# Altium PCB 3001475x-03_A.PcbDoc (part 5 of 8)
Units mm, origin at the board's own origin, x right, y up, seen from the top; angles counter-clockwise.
Board outline 100 x 72 mm, 12 copper layers (Top Layer, L2 GND, Layer 3, L4 GND, Layer 5, L6 PWR, L7 3V3, Layer 8, L9 GND, Layer 10, L11 GND, Bottom Layer), stack 1.735 mm thick; 428 components, 499 nets, 1973 pads, 1473 vias.
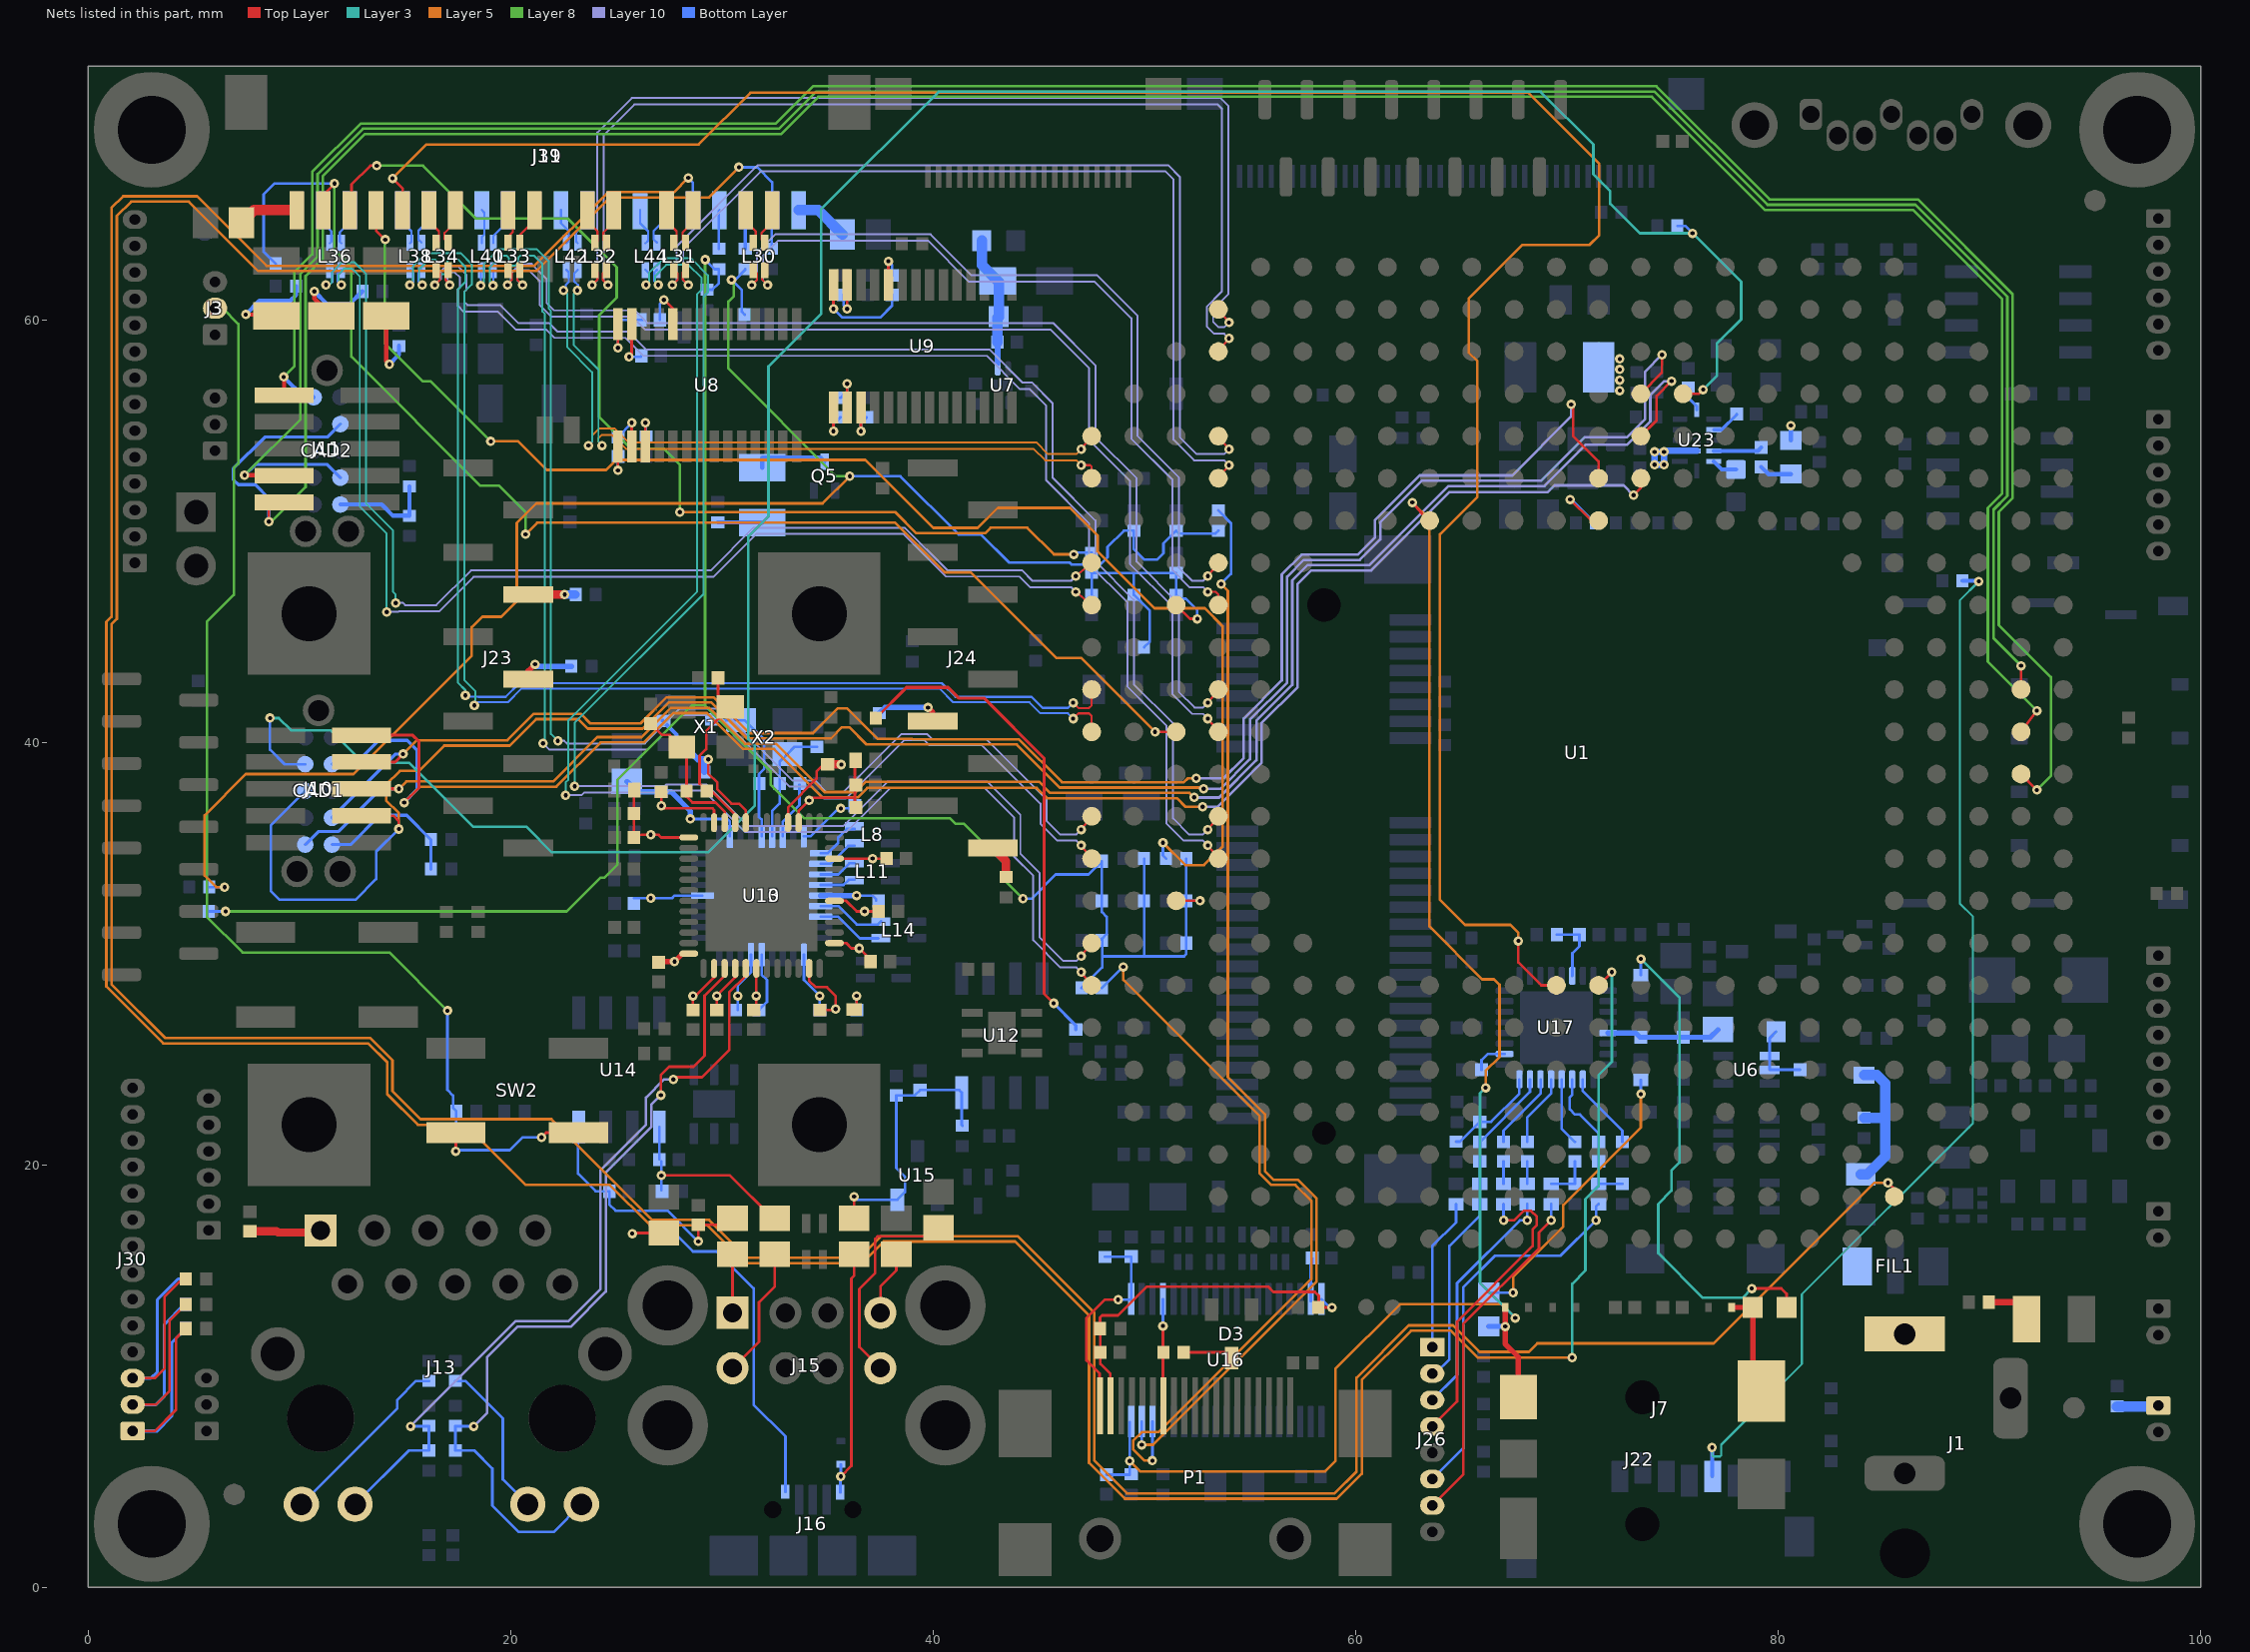
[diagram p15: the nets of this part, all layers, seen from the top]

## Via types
v1: diameter 0.45, hole 0.2, Top Layer to Bottom Layer, 1473 vias

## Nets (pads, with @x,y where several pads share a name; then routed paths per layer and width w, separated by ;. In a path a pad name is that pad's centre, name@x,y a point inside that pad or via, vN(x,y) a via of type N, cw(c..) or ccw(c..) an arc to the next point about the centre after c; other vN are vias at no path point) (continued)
HDMI_HPD: C83.2 R90.2 U1.G9 U16.19 | length 71
  Top Layer w0.125: v1(62.68,51.355) U1.G9@63.43,50.48
  Layer 5 w0.125: v1(49.305,5.98) 49.805,5.48 58.538,5.48 59.038,5.979 59.038,10.338 62.1,13.4 66.91,13.4 v1(67.555,12.755) ; v1(62.68,51.355) 63.487,50.548 63.487,31.279 65.979,28.788 66.546,28.788 66.805,28.528 66.805,25.105 66.15,24.45 v1(66.15,23.65)
  Layer 3 w0.125: v1(66.15,23.65) 65.887,23.387 65.887,14.423 v1(67.555,12.755)
  Bottom Layer w0.125: C83.2@48.2,5.335 49.305,5.335 v1(49.305,5.98) U16.19@49.305,7.83
HDMI_I2C_SCL: R99.2 U16.17 | length 35.6
  Layer 5 w0.125: v1(49,29.375) 49,28.75 55.45,22.3 55.45,19.6 56,19.05 57.15,19.05 57.9,18.3 57.9,14.592 50.658,7.35 49.875,7.35 49.462,6.937 49.462,6.538 50,6 v1(50.375,6)
  Bottom Layer w0.125: R99.2@47.98,28.375 48.98,29.375 v1(49,29.375) ; v1(50.375,6) U16.17@50.375,7.85
HDMI_I2C_SDA: R100.2 U16.18 | length 52.2
  Layer 5 w0.125: v1@49.875,6.625 v1(49.875,6.75) 50.412,6.75 58.15,14.488 58.15,18.404 57.254,19.3 56.104,19.3 55.704,19.7 55.704,22.4 53.95,24.154 53.95,47.175 v1(53.625,47.5)
  Bottom Layer w0.125: v1(49.875,6.75) U16.18@49.875,7.85 ; R100.2@53.5,50.98 54.1,50.38 54.1,47.975 v1(53.625,47.5)
HDMICEC: P1.13 R86.2 U16.23 | length 5.1
  Top Layer w0.125: P1.13@50.875,8.5 v1(50.875,12.375)
  Bottom Layer w0.125: v1(50.875,12.375) U16.23@50.875,13.65
HDMIHPD: C85.2 P1.19 R89.2 U16.20 | length 10.2
  Top Layer w0.125: P1.19@47.875,8.5 47.875,10.125 47.25,10.75 47.25,12.75 48.125,13.625 v1(48.75,13.625)
  Bottom Layer w0.125: R89.2@48.125,15.645 C85.2@49.355,15.645 ; v1(48.75,13.625) U16.20@49.35,13.625 ; U16.20@49.375,13.65 C85.2@49.375,15.645
I2C3_SCL: R95.1 R97.1 R99.1 R103.1 R106.1 R108.1 R109.1 R112.1 R114.1 R155.1 R207.1 R298.1 U1.T3 | length 98.9
  Top Layer w0.125: U1.T3@51.5,32.5 v1@52.625,32.5
  Layer 8 w0.125: v1(6.5,32) 22.65,32 24.237,33.587 24.421,33.587 25.05,34.217 25.05,38.233 28.567,41.75 29.2,41.75 ; v1(29.2,62.85) 29.2,41.75 ; v1(44.25,32.6) 43.5,33.35 43.5,34.099 41.447,36.152 41.049,36.152 40.788,36.412 33.888,36.412 32.3,38 32.3,38.65 29.2,41.75
  Bottom Layer w0.125: R155.1@5.705,32 v1(6.5,32) ; v1(29.2,62.85) 29.65,62.4 R298.1@29.85,62.4 29.85,61.742 29.538,61.43 R207.1@29.3,61.43 ; v1(44.25,32.6) 44.65,32.6 45.8,33.75 47.355,33.75 R108.1@47.98,34.375 47.98,31.97 48.213,31.737 48.213,30.933 R114.1@47.98,30.7 ; R99.1@47.02,28.375 48,29.355 48,29.875 ; R114.1@47.98,30.625 R114.1@47.98,30.7 ; R106.1@49.98,34.5 R103.1@49.98,32.5 49.98,29.875 ; R97.1@51.98,34.5 R95.1@51.98,32.5 ; v1(52.625,32.5) R95.1@51.98,32.5 ; R114.1@47.98,30.7 48,30.68 48,29.875 ; 48,29.875 49.98,29.875 ; 49.98,29.875 51.875,29.875 51.98,29.98 R109.1@51.98,30.5 R95.1@51.98,32.5
I2C3_SDA: R96.1 R98.1 R100.1 R105.1 R107.1 R110.1 R111.1 R113.1 R115.1 R156.1 R208.1 R299.1 U1.J3 | length 95.1
  Top Layer w0.125: U1.J3@51.5,46.5 52.15,45.85 v1(52.5,45.85)
  Layer 8 w0.125: v1@30.563,61.835 30.563,61.129 30.3,60.867 30.3,57.7 35.4,52.6 v1(36.05,52.6)
  Layer 5 w0.125: v1(6.45,33.15) 6.05,33.15 5.5,33.7 5.5,36.55 7.45,38.5 12.55,38.5 18.15,44.1 18.15,45.45 18.65,45.95 19.549,45.95 20.287,46.688 20.287,50.387 21.213,51.313 34.763,51.313 v1(36.05,52.6)
  Bottom Layer w0.125: R156.1@5.73,33.15 v1(6.45,33.15) ; v1(30.45,61.9) 30.937,61.413 30.937,60.383 R208.1@31.07,60.25 ; v1@30.628,61.9 31.1,62.372 R299.1@31.1,62.4 ; v1(36.05,52.6) 38.45,52.6 41.202,49.848 42.248,49.848 43.583,48.513 46.454,48.513 46.542,48.425 47.095,48.425 R98.1@47.5,48.02 ; R115.1@47.5,46.98 R98.1@47.5,48.02 ; R107.1@49.98,44.5 50.25,44.77 50.25,46.23 R111.1@49.5,46.98 49.5,48.02 ; v1(52.5,45.85) 52.5,46.262 51.962,46.8 51.68,46.8 R96.1@51.5,46.98 R105.1@51.5,48.02 49.5,48.02 ; R100.1@53.5,50.02 53.367,49.887 51.633,49.887 R113.1@51.5,50.02 50.9,49.42 50.9,48.95 50.6,48.65 50,48.65 49.5,49.15 R110.1@49.5,50.02 49.02,50.02 48.25,49.25 48.25,48.77 R98.1@47.5,48.02 ; R98.1@47.5,48.02 49.5,48.02
JTAG_MOD: R37.2 U1.G13 | length 3.5
  Top Layer w0.125: v1(70.15,51.5) 71.15,50.5 U1.G13@71.5,50.5 U1.G13@71.5,50.6
  Bottom Layer w0.125: v1(70.15,51.5) 70.217,51.5 71.317,50.4 R37.2@71.38,50.4
JTAG_TCK: CAD1.4 J10.4 U1.F13 | length 82.5
  Top Layer w0.125: v1(70.2,56) 70.287,55.913 70.287,54.513 71.5,53.3 U1.F13@71.5,52.5
  Top Layer w0.15: J10.4@12.932,39.07 14.52,39.07 v1(14.9,39.45)
  Layer 5 w0.125: v1(14.9,39.45) 15.548,40.098 19.844,40.098 21.096,41.35 23.3,41.35 23.75,40.9 26.139,40.9 27.377,42.138 29.598,42.138 31.298,40.437 34.312,40.437 35.487,41.613 35.921,41.613 37.371,40.163 38.999,40.163 39.012,40.15 44.054,40.15 46.091,38.113 51.859,38.113 52.046,38.3 v1(52.45,38.3)
  Layer 10 w0.125: v1(52.45,38.3) 53.739,38.3 54.7,39.261 54.7,41.136 56.5,42.936 56.5,47.95 57.437,48.887 60.087,48.887 60.913,49.713 60.913,50.524 63.026,52.637 67.421,52.637 70.2,55.417 v1(70.2,56) v1@70.187,56.013
  Bottom Layer w0.15: CAD1.4@11.535,36.43 14.555,39.45 v1(14.9,39.45)
JTAG_TDI: CAD1.8 J10.8 U1.D14 | length 99.5
  Top Layer w0.125: J10.8@12.932,36.53 14.435,36.53 14.7,36.265 v1(14.7,35.9) ; U1.D14@73.5,56.5 74.5,57.5 v1(74.5,58.35)
  Layer 5 w0.125: v1(14.7,35.9) 14.7,36.65 14.1,37.25 14.1,38 14.75,38.65 15.65,38.65 16.848,39.848 19.948,39.848 21.2,41.1 23.196,41.1 23.646,40.65 26.243,40.65 27.48,41.888 29.495,41.888 31.195,40.187 35.154,40.187 35.679,40.713 36.021,40.713 36.821,39.913 38.896,39.913 38.908,39.9 43.95,39.9 45.987,37.863 52.737,37.863 v1(52.8,37.8)
  Layer 10 w0.125: v1(52.8,37.8) 53.593,37.8 54.995,39.202 54.995,41.077 56.75,42.832 56.75,47.846 57.541,48.637 60.191,48.637 61.163,49.609 61.163,50.421 63.129,52.387 68.781,52.387 70.844,54.45 72.85,54.45 73.7,55.3 73.7,57.55 v1(74.5,58.35)
  Bottom Layer w0.125: CAD1.8@10.265,37.7 8.65,36.085 8.65,32.95 9.05,32.55 12.65,32.55 13.625,33.525 13.625,34.825 v1(14.7,35.9)
JTAG_TDO: CAD1.6 J10.6 U1.E14 | length 87.4
  Top Layer w0.125: U1.E14@73.5,54.5 74.25,55.25 74.25,56.4 v1(74.95,57.1)
  Top Layer w0.15: J10.6@12.932,37.8 v1(14.7,37.8)
  Layer 5 w0.125: v1(14.7,37.8) 15.05,38.15 22,38.15 24.1,40.25 26.196,40.25 27.584,41.638 29.391,41.638 31.091,39.937 32.563,39.937 34.85,37.65 36.328,37.65 36.814,38.136 45.014,38.136 45.537,37.613 52.137,37.613 v1(52.35,37.4)
  Layer 10 w0.125: v1(52.35,37.4) 52.363,37.387 53.534,37.387 55.3,39.154 55.3,41.029 57,42.729 57,47.675 57.712,48.387 60.637,48.387 64.387,52.137 68.937,52.137 70.896,54.096 72.85,54.096 73.95,55.196 73.95,56.45 74.6,57.1 v1(74.95,57.1)
  Bottom Layer w0.15: CAD1.6@10.265,35.16 10.884,35.779 11.829,35.779 13.85,37.8 v1(14.7,37.8)
JTAG_TMS: CAD1.2 J10.2 U1.F14 | length 87
  Top Layer w0.125: v1(14.95,37.15) 15.65,37.85 15.65,39.15 ; v1(73.15,51.7) 73.5,52.05 U1.F14@73.5,52.5
  Top Layer w0.15: J10.2@12.932,40.34 15.36,40.34 15.65,40.05 15.65,39.15
  Layer 5 w0.125: v1(14.95,37.15) 15.7,37.9 22.15,37.9 24.25,40 26.3,40 27.688,41.388 29.288,41.388 30.988,39.687 32.459,39.687 34.746,37.4 36.432,37.4 36.882,37.85 44.9,37.85 45.387,37.363 51.537,37.363 51.95,36.95 v1(52.75,36.95)
  Layer 10 w0.125: v1(52.75,36.95) 53.45,36.95 55.55,39.05 55.55,40.925 57.25,42.625 57.25,47.5 57.887,48.137 60.741,48.137 64.454,51.85 69.096,51.85 69.409,52.163 72.687,52.163 v1(73.15,51.7)
  Bottom Layer w0.15: CAD1.2@11.535,38.97 12.62,38.97 13.75,40.1 15.1,40.1 15.55,39.65 15.55,37.75 v1(14.95,37.15)
JTAG_TRST_N: CAD1.9 R36.1 U1.D15 | length 118.2
  Top Layer w0.125: U1.D15@75.5,56.5 76.25,56.5 v1(76.45,56.7)
  Layer 3 w0.125: v1(8.6,41.15) 9.017,41.15 9.593,40.573 11.477,40.573 13.013,39.037 15.183,39.037 18.22,36 20.75,36 21.95,34.8 29.35,34.8 31.55,37 31.55,39.85 31.25,40.15 31.25,49.75 32.2,50.7 32.2,57.8 34.7,60.3 34.7,65.25 40.253,70.803 68.747,70.803 71.25,68.3 71.25,66.9 72.05,66.1 72.05,65.5 73.45,64.1 v1(75.95,64.1) 78.25,61.8 78.25,60.025 77.1,58.875 77.1,57.35 v1(76.45,56.7)
  Bottom Layer w0.125: v1(8.6,41.15) 8.6,39.65 9.28,38.97 CAD1.9@10.265,38.97 ; R36.1@75.23,64.45 75.6,64.45 v1(75.95,64.1)
LED1/PHYAD0: J13.D2 R53.1 R54.1 U10.17 | length 38.4
  Top Layer w0.125: v1(27.7,24.05) 27.8,24.15 29.05,24.15 30.337,25.437 30.337,28.171 31.125,28.958 U10.17@31.125,29.3
  Layer 10 w0.125: v1(15.25,7.625) 20.225,12.6 22.725,12.6 24.25,14.125 24.25,19.75 26.4,21.9 26.4,23.183 27.267,24.05 v1(27.7,24.05)
  Bottom Layer w0.125: J13.D2@12.626,3.936 15.17,6.48 R54.1@16.125,6.48 ; v1(15.25,7.625) R53.1@16.105,7.625 ; R53.1@16.125,7.625 R54.1@16.125,6.48 ; R53.1@16.125,7.645 R54.1@16.125,6.48
LED2/PHYAD1: J13.D4 R55.1 R56.1 U10.15 | length 41
  Top Layer w0.125: v1(27.1,23.3) 27.1,24.25 27.5,24.65 28.65,24.65 29.175,25.175 29.175,28.008 30.125,28.958 U10.15@30.125,29.3
  Layer 10 w0.125: v1(18.25,7.625) 18.875,8.25 18.875,10.896 20.329,12.35 22.85,12.35 24.5,14 24.5,19.646 26.65,21.796 26.65,22.85 v1(27.1,23.3)
  Bottom Layer w0.125: R55.1@17.375,7.625 R56.1@17.375,6.48 ; R55.1@17.375,7.645 R56.1@17.375,6.48 ; R55.1@17.395,7.625 v1(18.25,7.625) ; J13.D4@23.344,3.936 22.033,2.625 20.375,2.625 19.125,3.875 19.125,5.625 18.27,6.48 R56.1@17.375,6.48
LINE_IN_L: J26.4 L21.1 | length 14.6
  Top Layer w0.125: J26.4@63.625,7.625 64.8,8.8 64.8,12.575 68.375,16.15 68.375,16.95 68.575,17.15 68.575,17.55 68.3,17.825 67.95,17.825 67.5,17.375 v1(67,17.375)
  Bottom Layer w0.125: v1(67,17.375) L21.1@67,18.145
LINE_IN_R: J26.3 L20.1 | length 11.3
  Bottom Layer w0.125: J26.3@63.625,8.875 64.8,10.05 64.8,14.4 67.775,17.375 v1(68.125,17.375) L20.1@68.125,18.145
LINE_OUT_L: J26.7 L19.2 | length 16.6
  Top Layer w0.125: J26.7@63.625,3.875 65.087,5.337 65.087,12.462 68.675,16.05 68.675,16.8 v1(69.25,17.375)
  Bottom Layer w0.125: v1(69.25,17.375) L19.2@69.25,18.145
LINE_OUT_R: J26.6 L18.2 | length 18.1
  Bottom Layer w0.125: J26.6@63.625,5.125 65.087,6.587 65.087,14.187 66.6,15.7 69.7,15.7 v1(71.375,17.375) 71.375,18.02 L18.2@71.5,18.145
LVDS0_CLK_N: L33.1 U1.M4 | length 51.3
  Top Layer w0.104: L33.1@20.425,62.375 20.308,62.258 20.308,61.892 v1(20.551,61.649) ; v1(53,41.125) U1.M4@53.5,40.5
  Layer 10 w0.093: v1(20.551,61.649) 20.3,61.9 20.3,62.075 20.575,62.35 20.866,62.35 21.366,61.85 21.366,61.484 ; 21.366,61.609 21.366,61.484 ; v1(53,41.125) 52.775,41.35 52.251,41.35 51.325,42.276 51.325,46.425 49.325,48.425 49.325,52.376 47.375,54.326 47.375,57.725 45.55,59.55 26.35,59.55 25.75,60.15 21.926,60.15 21.366,60.709 21.366,61.484
LVDS0_CLK_P: L33.4 U1.L4 | length 51.7
  Top Layer w0.104: v1(19.85,61.65) 19.85,61.697 20.053,61.9 20.053,62.197 L33.4@19.875,62.375 ; v1(53,41.875) U1.L4@53.5,42.5
  Layer 10 w0.093: v1(19.85,61.65) 19.85,61.697 20,61.847 20,62.199 20.451,62.65 20.991,62.65 21.691,61.95 21.691,61.609 21.691,60.809 22.05,60.45 25.874,60.45 26.474,59.85 45.674,59.85 47.675,57.849 47.675,54.45 49.625,52.5 49.625,48.549 51.625,46.549 51.625,42.4 52.375,41.65 52.775,41.65 v1(53,41.875)
LVDS0_CONTRAST: J19.16 U1.V12 | length 110.1
  Top Layer w0.125: v1(14.4,66.7) 14.875,66.225 J19.16@14.875,65.2 ; v1(67.7,30.6) 67.7,29.583 68.783,28.5 U1.V12@69.5,28.5
  Layer 5 w0.125: v1(14.4,66.7) 16,68.3 28.9,68.3 31.35,70.75 68.175,70.75 71.525,67.4 71.525,64 71.075,63.55 67.9,63.55 65.35,61 65.35,58.463 65.763,58.05 65.763,51.62 63.987,49.845 63.987,32.554 65.179,31.363 67.321,31.363 67.7,30.983 v1(67.7,30.6)
LVDS0_I2C_SCL: J19.17 R97.2 | length 68.2
  Top Layer w0.125: J19.17@13.625,65.2 13.625,64.225 v1(14.05,63.8)
  Layer 8 w0.125: v1(14.05,63.8) 14.037,63.787 14.037,58.879 15.829,57.087 16.213,57.087 v1(19.05,54.25)
  Layer 5 w0.125: v1(19.05,54.25) 20.35,54.25 21.7,52.9 24.512,52.9 24.979,53.368 36.782,53.368 39.998,50.152 42.102,50.152 43.05,51.1 46.475,51.1 47.775,49.8 47.775,49.05 50.475,46.35 52.85,46.35 53.7,45.5 53.7,35.067 52.821,34.187 51.938,34.187 v1(50.875,35.25)
  Bottom Layer w0.125: v1(50.875,35.25) 50.875,34.645 R97.2@51.02,34.5
LVDS0_I2C_SDA: J19.18 R98.2 | length 51.2
  Top Layer w0.125: J19.18@12.375,65.2 12.463,65.287 12.463,66.413 13.35,67.3 v1(13.65,67.3)
  Layer 8 w0.125: v1(13.65,67.3) 15.85,67.3 18.35,64.8 22.7,64.8 25.014,62.486 25.014,61.05 24.187,60.223 24.187,55.413 25.7,53.9 27.25,53.9 28,53.15 v1(28,50.9)
  Layer 5 w0.125: v1(28,50.9) 38.2,50.9 39.198,49.902 42.452,49.902 42.713,50.163 44.45,50.163 45.713,48.9 v1(46.65,48.9)
  Bottom Layer w0.125: v1(46.65,48.9) 46.73,48.98 R98.2@47.5,48.98
LVDS0_IRQ_N: J19.19 R76.2 U1.M3 | length 64.6
  Top Layer w0.125: J19.19@11.125,65.2 11.125,65.925 v1(11.65,66.45) ; v1(50.5,40.5) U1.M3@51.5,40.5
  Layer 8 w0.125: v1(11.65,66.45) 11.65,63.3 12.45,62.5 12.45,58.267 18.565,52.152 19.447,52.152 20.7,50.899 v1(20.7,49.85)
  Layer 5 w0.125: v1(20.7,49.85) 21.25,50.4 38.2,50.4 40.55,48.05 41.775,48.05 45.825,44 47,44 v1(50.5,40.5)
  Bottom Layer w0.125: R76.2@8.87,62.65 8.3,63.22 8.3,65.95 8.8,66.45 v1(11.65,66.45)
LVDS0_TX0_N: L30.1 U1.J4 | length 37.4
  Top Layer w0.104: L30.1@32.025,62.375 31.9,62.25 31.9,61.9 v1(32.153,61.647) ; v1(53,47.125) 53.375,47.125 53.5,47 U1.J4@53.5,46.55
  Layer 10 w0.093: v1(32.153,61.647) 31.95,61.85 31.95,63.05 32.65,63.75 33.484,63.75 33.816,63.751 39.75,63.75 41.692,61.808 47.642,61.808 49.375,60.076 49.375,54.375 51.325,52.425 51.325,48.151 52.126,47.35 52.775,47.35 v1(53,47.125)
LVDS0_TX0_P: L30.4 U1.H4 | length 37.8
  Top Layer w0.104: v1(31.403,61.647) 31.653,61.897 31.653,62.197 L30.4@31.475,62.375 ; v1(53,47.875) U1.H4@53.5,48.5
  Layer 10 w0.093: v1(31.403,61.647) 31.65,61.894 31.65,63.174 32.526,64.05 33.359,64.05 ; 33.36,64.051 33.94,64.051 39.874,64.05 41.816,62.108 47.767,62.108 49.675,60.2 49.675,54.499 51.625,52.549 51.625,48.275 52.25,47.65 52.775,47.65 v1(53,47.875)
LVDS0_TX1_N: L31.1 U1.F4 | length 43.8
  Top Layer w0.104: L31.1@28.275,62.375 28.149,62.249 28.149,61.901 v1(28.4,61.65) ; U1.F4@53.5,52.5 v1(54,53.125)
  Layer 10 w0.093: v1(28.4,61.65) 28.15,61.9 28.15,63.35 31.825,67.025 51,67.025 51.375,66.65 51.375,54.326 52.351,53.35 53.775,53.35 v1(54,53.125)
LVDS0_TX1_P: L31.4 U1.E4 | length 44.3
  Top Layer w0.104: v1(27.65,61.65) 27.902,61.902 27.902,62.198 L31.4@27.725,62.375 ; U1.E4@53.5,54.5 v1(54,53.875)
  Layer 10 w0.093: v1(27.65,61.65) 27.85,61.85 27.85,63.474 31.701,67.325 51.124,67.325 51.675,66.774 51.675,54.45 52.475,53.65 53.775,53.65 v1(54,53.875)
LVDS0_TX2_N: L32.1 U1.C4 | length 50.7
  Top Layer w0.104: L32.1@24.525,62.375 24.35,62.2 24.35,61.9 v1(24.601,61.649) ; U1.C4@53.5,58.5 v1(54,59.125)
  Layer 10 w0.093: v1(24.601,61.649) 24.4,61.85 24.4,68.75 25.85,70.2 53.475,70.2 53.663,70.012 53.663,61.337 52.95,60.624 52.95,59.7 53.3,59.35 53.775,59.35 v1(54,59.125)
LVDS0_TX2_P: L32.4 U1.B4 | length 51.2
  Top Layer w0.104: v1(23.851,61.649) 24.103,61.9 24.103,62.247 L32.4@23.975,62.375 ; U1.B4@53.5,60.5 v1(54,59.875)
  Layer 10 w0.093: v1(23.851,61.649) 24.1,61.897 24.1,68.874 25.726,70.5 53.599,70.5 53.963,70.136 53.963,61.213 53.25,60.5 53.25,59.9 53.5,59.65 53.775,59.65 v1(54,59.875)
LVDS0_TX3_N: L34.1 U1.R4 | length 58.7
  Top Layer w0.104: L34.1@17.025,62.375 16.9,62.25 16.9,61.9 17.1,61.7 v1(17.1,61.65) ; v1(53,35.125) U1.R4@53.5,34.5
  Layer 10 w0.093: v1(17.1,61.65) 17.1,61.7 17,61.8 17,62.175 17.075,62.25 17.35,62.25 17.6,62 17.6,61.55 17.497,61.447 17.497,60.654 17.75,60.4 19.376,60.4 20.226,59.55 21.676,59.55 22.076,59.15 25.426,59.15 26.276,58.3 42.532,58.3 44.108,56.724 44.565,56.724 45.35,55.939 45.35,52.401 47.375,50.376 47.375,48.451 49.2,46.626 49.2,42.626 51.05,40.776 51.05,36.15 51.85,35.35 52.775,35.35 v1(53,35.125)
LVDS0_TX3_P: L34.4 U1.P4 | length 59.2
  Top Layer w0.104: v1(16.401,61.649) 16.645,61.892 16.645,62.205 L34.4@16.475,62.375 ; v1(53,35.875) U1.P4@53.5,36.5
  Layer 10 w0.093: v1(16.401,61.649) 16.688,61.935 16.688,62.287 16.951,62.55 17.474,62.55 17.9,62.124 17.9,61.426 17.796,61.322 17.796,60.854 17.95,60.7 19.5,60.7 20.35,59.85 21.8,59.85 22.2,59.45 25.55,59.45 26.4,58.6 42.656,58.6 44.232,57.024 44.689,57.024 45.65,56.063 45.65,52.525 47.675,50.5 47.675,48.575 49.5,46.75 49.5,42.75 51.35,40.9 51.35,36.4 52.1,35.65 52.775,35.65 v1(53,35.875)
LVDS1_CLK_N: L42.1 U1.E1 | length 34.4
  Top Layer w0.104: v1(47,53.875) U1.E1@47.5,54.5
  Layer 5 w0.093: v1(23.676,54.05) 23.85,54.225 23.85,54.524 24.176,54.85 24.924,54.85 25.574,54.2 44.875,54.2 45.425,53.65 46.775,53.65 v1(47,53.875)
  Layer 3 w0.093: v1(22.5,61.4) 22.675,61.225 22.675,58.701 23.85,57.526 23.85,54.225 v1(23.676,54.05)
  Bottom Layer w0.104: v1(22.5,61.4) 22.575,61.4 22.602,61.427 22.602,61.652 22.745,61.795 22.745,62.255 L42.1@22.625,62.375
LVDS1_CLK_P: L42.4 U1.F1 | length 34.1
  Top Layer w0.104: v1(47,53.125) 47.425,53.125 47.5,53.05 U1.F1@47.5,52.5
  Layer 5 w0.093: v1(24.325,54.05) 24.15,54.225 24.15,54.4 24.3,54.55 24.8,54.55 25.45,53.9 44.751,53.9 45.301,53.35 46.775,53.35 v1(47,53.125)
  Layer 3 w0.093: v1(23.15,61.4) 22.975,61.225 22.975,58.825 24.15,57.65 24.15,54.225 v1(24.325,54.05)
  Bottom Layer w0.104: 23,61.828 23.177,61.652 23.177,61.427 v1(23.15,61.4) ; 23,61.828 23,62.2 L42.4@23.175,62.375
LVDS1_CONTRAST: J31.16 U1.V13 | length 180.8
  Top Layer w0.125: U1.V13@71.5,28.5 v1(72.125,29.125)
  Layer 5 w0.125: v1(28.4,66.723) 27.727,66.05 24.6,66.05 21.113,62.563 8.437,62.563 5.15,65.85 1.646,65.85 1.1,65.304 1.1,45.95 0.85,45.7 0.85,28.45 3.55,25.75 13.25,25.75 14.15,24.85 14.15,23.35 15.6,21.9 17.85,21.9 20.7,19.05 24.686,19.05 26.586,17.15 29.289,17.15 31.089,15.35 36.625,15.35 37.275,16 37.65,16.375 43.875,16.375 47.375,12.875 47.375,5.896 49.071,4.2 58.896,4.2 59.104,4.2 60.288,5.384 60.288,9.82 62.618,12.15 64.507,12.15 65.782,10.875 v1(70.25,10.875)
  Layer 3 w0.125: v1(70.25,10.875) 70.25,14.375 70.875,15 70.875,18.375 71.5,19 71.5,24.25 72.125,24.875 v1(72.125,29.125)
  Bottom Layer w0.125: v1(28.4,66.723) 28.625,66.498 J31.16@28.625,65.2
LVDS1_I2C_SCL: J31.17 R298.2 | length 1.9
  Bottom Layer w0.101: R298.2@29.85,63.36 29.85,65.175 J31.17@29.875,65.2
LVDS1_I2C_SDA: J31.18 R299.2 | length 1.9
  Bottom Layer w0.15: R299.2@31.1,63.36 31.1,65.175 J31.18@31.125,65.2
LVDS1_IRQ_N: J31.19 R118.2 U1.AC20 | length 185
  Top Layer w0.125: v1(85.2,19.15) 85.5,18.85 U1.AC20@85.5,18.5
  Layer 5 w0.125: v1(30.8,67.225) 30.8,67.217 29.383,65.8 24.704,65.8 21.216,62.313 8.037,62.313 4.75,65.6 2.029,65.6 1.35,64.921 1.35,45.846 1.1,45.596 1.1,28.554 3.654,26 13.354,26 14.4,24.954 14.4,23.489 15.727,22.163 21.927,22.163 26.689,17.4 29.393,17.4 31.193,15.6 36.521,15.6 37.171,16.25 37.546,16.625 44,16.625 47.625,13 47.625,6 49.175,4.45 59,4.45 60.038,5.488 60.038,9.923 62.514,12.4 64.611,12.4 65.861,11.15 68.2,11.15 68.6,11.55 76.944,11.55 84.544,19.15 v1(85.2,19.15)
  Bottom Layer w0.125: v1(30.8,67.225) 31.675,67.225 32.375,66.525 J31.19@32.375,65.2 32.35,65.175 R118.2@32.35,63.36
LVDS1_TX0_N: L36.1 U1.H1 | length 55.6
  Top Layer w0.104: v1(46.75,47.875) U1.H1@47.5,48.5
  Layer 10 w0.093: v1(14.55,46.6) 14.9,46.6 15,46.5 16.475,46.5 18.111,48.136 29.462,48.136 31.489,50.163 38.65,50.163 40.663,48.15 44.199,48.15 44.699,47.65 46.525,47.65 v1(46.75,47.875)
  Layer 3 w0.093: v1@11.402,61.652 11.539,61.789 11.539,62.264 12.002,62.727 12.602,62.727 13.15,62.178 13.15,51.3 14.425,50.025 14.425,47.125 14.55,47 v1(14.55,46.6)
  Bottom Layer w0.104: v1@11.402,61.652 11.552,61.802 11.552,62.248 L36.1@11.425,62.375
  other v1: 11.252,61.652
LVDS1_TX0_P: L36.4 U1.J1 | length 55.4
  Top Layer w0.104: v1(46.75,47.125) U1.J1@47.5,46.5
  Layer 10 w0.093: v1(14.125,46.175) 14.675,46.175 14.7,46.2 16.599,46.2 18.235,47.836 29.586,47.836 31.613,49.863 38.6,49.863 40.613,47.85 44.075,47.85 44.575,47.35 46.525,47.35 v1(46.75,47.125)
  Layer 3 w0.093: v1(11.977,61.652) 11.839,61.789 11.839,62.139 12.127,62.427 12.477,62.427 12.85,62.054 12.85,51.15 14.125,49.875 v1(14.125,46.175)
  Bottom Layer w0.104: 11.8,61.828 11.8,62.2 L36.4@11.975,62.375 ; 11.8,61.828 v1(11.977,61.652)
LVDS1_TX1_N: L38.1 U1.M1 | length 57.4
  Top Layer w0.104: v1(46.625,41.125) 46.872,41.373 47.375,41.373 47.5,41.247 U1.M1@47.5,40.5
  Layer 3 w0.093: v1(15.225,61.65) 15.363,61.788 15.363,62.524 16.001,63.162 17.624,63.162 18.15,62.637 18.15,61.676 17.796,61.322 17.796,42.95 18.324,42.422 18.324,41.799 v1(18.275,41.75)
  Bottom Layer w0.104: v1(15.225,61.65) 15.376,61.801 15.376,62.224 L38.1@15.225,62.375 ; v1(18.275,41.75) 18.424,41.899 19.856,41.899 20.508,42.55 40.292,42.55 40.944,41.899 44.552,41.899 45.073,41.378 46.372,41.378 v1(46.625,41.125)
LVDS1_TX1_P: L38.4 U1.L1 | length 57.4
  Top Layer w0.104: v1(46.625,41.875) 46.872,41.628 47.375,41.628 47.5,41.753 U1.L1@47.5,42.5
  Layer 3 w0.093: v1(15.8,61.65) 15.663,61.787 15.663,62.4 16.125,62.862 16.425,62.862 16.5,62.787 16.5,62.287 16.625,62.162 16.875,62.162 17,62.287 17,62.787 17.075,62.862 17.5,62.862 17.85,62.512 17.85,61.8 17.497,61.447 17.497,42.825 17.85,42.472 v1(17.85,42.225)
  Bottom Layer w0.104: 15.624,61.826 v1(15.8,61.65) ; 15.623,61.827 15.623,62.223 L38.4@15.775,62.375 ; v1(17.85,42.225) 17.906,42.169 18.449,42.169 18.464,42.154 19.751,42.154 20.402,42.805 40.398,42.805 41.049,42.154 44.658,42.154 45.178,41.633 46.383,41.633 v1(46.625,41.875)
LVDS1_TX2_N: L40.1 U1.P1 | length 60.2
  Top Layer w0.104: v1(47,35.875) U1.P1@47.5,36.5
  Layer 10 w0.093: v1(22.225,40.075) 22.525,40.075 22.65,39.95 26.351,39.95 28.001,41.6 29.925,41.6 31.125,40.4 33.325,38.2 34.4,38.2 34.961,37.639 35.731,37.639 38.491,40.4 39.7,40.4 ; 39.788,40.312 39.7,40.4 ; v1(47,35.875) 46.775,35.65 46,35.65 45.375,36.275 45.375,37.275 42.486,40.164 39.936,40.164 39.7,40.4
  Layer 3 w0.093: v1(18.578,61.625) 18.716,61.763 18.716,62.624 19.429,63.338 21.237,63.338 21.8,62.774 21.8,60.524 21.9,60.424 21.9,40.4 v1(22.225,40.075)
  Bottom Layer w0.104: v1(18.578,61.625) 18.578,62.303 L40.1@18.625,62.35
LVDS1_TX2_P: L40.4 U1.R1 | length 60.5
  Top Layer w0.104: v1(47,35.125) U1.R1@47.5,34.5
  Layer 10 w0.093: v1(21.525,39.95) 21.825,39.65 26.475,39.65 28.125,41.3 29.801,41.3 31.001,40.1 33.201,37.9 34.276,37.9 34.836,37.339 35.855,37.339 38.616,40.1 39.576,40.1 39.812,39.864 42.311,39.864 45.075,37.1 45.075,36.151 45.876,35.35 46.775,35.35 v1(47,35.125)
  Layer 3 w0.093: v1(19.153,61.625) 19.016,61.763 19.016,62.5 19.553,63.038 19.813,63.038 19.9,62.95 19.9,62.65 19.987,62.563 20.213,62.563 20.35,62.7 20.35,62.95 20.438,63.038 21.113,63.038 21.5,62.65 21.5,60.4 21.6,60.3 21.6,40.025 v1(21.525,39.95)
  Bottom Layer w0.104: v1(19.153,61.625) 19.175,61.647 L40.4@19.175,62.35
LVDS1_TX3_N: L44.1 U1.U1 | length 64.7
  Top Layer w0.104: v1(47,29.875) U1.U1@47.5,30.5
  Layer 10 w0.093: v1(23.025,37.925) 27.276,37.925 27.364,38.013 29.261,38.013 31.224,36.05 35.75,36.05 37.836,38.136 42.563,38.136 44.125,36.574 44.125,34.725 45.038,33.812 45.038,30.761 46.149,29.65 46.775,29.65 v1(47,29.875)
  Layer 3 w0.093: v1(23.025,37.925) 23.025,40.925 29.125,47.025 29.125,61.1 29.338,61.313 29.338,62.112 28.537,62.912 27.238,62.912 26.539,62.213 26.539,61.789 v1(26.402,61.652)
  Bottom Layer w0.104: L44.1@26.375,62.375 26.552,62.198 26.552,61.802 v1(26.402,61.652)
LVDS1_TX3_P: L44.4 U1.V1 | length 64.6
  Top Layer w0.104: v1(47,29.125) U1.V1@47.5,28.5
  Layer 10 w0.093: v1(22.6,37.5) 23.35,37.5 23.475,37.625 27.4,37.625 27.488,37.713 29.137,37.713 31.1,35.75 35.874,35.75 37.96,37.836 42.439,37.836 43.825,36.45 43.825,34.601 44.738,33.688 44.738,30.637 46.025,29.35 46.775,29.35 v1(47,29.125)
  Layer 3 w0.093: v1(22.6,37.5) 22.6,38.1 22.725,38.225 22.725,41.049 28.825,47.149 28.825,61.224 29.038,61.437 29.038,61.988 28.413,62.612 27.362,62.612 26.839,62.089 26.839,61.789 v1(26.977,61.652)
  Bottom Layer w0.104: 26.8,61.828 26.8,62.25 L44.4@26.925,62.375 ; 26.8,61.828 v1(26.977,61.652)
MCA_RESET_N: CAD2.10 J11.10 U1.N23 | length 125.3
  Top Layer w0.125: U1.N23@91.5,38.5 v1(92.25,37.75)
  Top Layer w0.2: v1(9.25,57.3) 9.268,57.282 J11.10@9.268,56.44
  Layer 8 w0.125: v1(9.25,57.3) 9.75,57.8 9.75,62.25 10.6,63.1 10.6,67 12.9,69.3 32.55,69.3 34.313,71.063 74.235,71.063 79.598,65.7 86.607,65.7 91.1,61.207 91.1,51.564 90.45,50.914 90.45,45.55 92.913,43.087 92.913,38.413 v1(92.25,37.75)
  Bottom Layer w0.2: v1(9.25,57.3) 10.21,56.34 CAD2.10@10.665,56.34
MCA_SWD_CLK: CAD2.4 J11.4 U1.L23 | length 127.6
  Top Layer w0.125: U1.L23@91.5,42.5 v1(91.5,43.625)
  Top Layer w0.2: v1(7.4,52.65) 9.248,52.65 J11.4@9.268,52.63
  Layer 8 w0.125: v1(7.4,52.65) 10.037,55.287 10.037,62.184 10.85,62.996 10.85,66.896 13.004,69.05 32.7,69.05 34.463,70.813 74.132,70.813 79.494,65.45 86.504,65.45 90.85,61.104 90.85,51.668 90.2,51.018 90.2,44.925 v1(91.5,43.625)
  Bottom Layer w0.15: v1(7.4,52.65) 7.9,53.15 11.315,53.15 CAD2.4@11.935,52.53
MCA_SWD_DIO: CAD2.2 J11.2 U1.M23 | length 135.7
  Top Layer w0.125: v1(8.55,50.45) 8.55,51.36 J11.2@9.268,51.36 ; U1.M23@91.5,40.5 v1(92.25,41.5)
  Layer 8 w0.125: v1(8.55,50.45) 8.65,50.45 10.287,52.087 10.287,62.08 11.1,62.893 11.1,66.793 13.107,68.8 32.804,68.8 34.566,70.563 74.028,70.563 79.39,65.2 86.4,65.2 90.6,61 90.6,51.771 89.925,51.096 89.925,43.825 v1(92.25,41.5)
  Bottom Layer w0.15: v1(8.55,50.45) 8.55,51.55 7.9,52.2 7.1,52.2 6.85,52.45 6.85,52.95 8.35,54.45 11.315,54.45 CAD2.2@11.935,55.07
MIC_BIAS: J26.1 L23.1 | length 7.2
  Bottom Layer w0.125: J26.1@63.625,11.375 63.625,16.15 64.75,17.275 L23.1@64.75,18.145
MIC_IN: J26.2 L22.1 | length 8.9
  Bottom Layer w0.125: J26.2@63.765,10.125 64.44,10.8 64.44,16.165 65.875,17.6 L22.1@65.875,18.145
NetC4_2: C4.2 R15.2 U6.1 U6.2 | length 3.4
  Bottom Layer w0.15: R15.2@79.9,26.3 79.6,26 U6.1@79.6,25.15 U6.2@79.6,24.5 C4.2@81.04,24.5
NetC8_2: C8.2 C9.1 C10.2 R21.1 U7.1 | length 6.2
  Bottom Layer w0.3: C10.2@43.04,58.95 43.05,58.94 U7.1@43.05,57.96
  Bottom Layer w0.5: R21.1@42.3,63.75 42.3,62.6 C9.1@43.05,61.85 43.1,61.8 C8.2@43.1,60.15 43.04,60.09 C10.2@43.04,58.95
NetC18_1: C18.1 U8.24 | length 2.3
  Top Layer w0.125: v1(27.25,60.95) 27.675,60.525 U8.24@27.675,59.805
  Bottom Layer w0.125: C18.1@27.06,60 27.06,60.76 v1(27.25,60.95)
NetC18_2: C18.2 U8.28 | length 3.5
  Top Layer w0.125: v1(25.075,58.68) U8.28@25.075,59.805
  Bottom Layer w0.125: v1(25.075,58.68) 25.075,59.825 25.25,60 C18.2@26.24,60
NetC19_1: C19.1 U8.27 | length 2.2
  Top Layer w0.125: v1(25.6,58.25) 25.725,58.375 U8.27@25.725,59.805
  Bottom Layer w0.125: v1(25.6,58.25) 26.14,58.25 C19.1@26.19,58.3
NetC20_1: C20.1 U9.24 | length 1.9
  Top Layer w0.125: U9.24@37.875,61.65 v1(37.875,62.775)
  Bottom Layer w0.125: v1(37.875,62.775) 38.05,62.6 C20.1@38.05,62.11
NetC20_2: C20.2 U9.28 | length 4.8
  Top Layer w0.125: v1(35.275,60.525) U9.28@35.275,61.65
  Bottom Layer w0.125: v1(35.275,60.525) 35.688,60.112 37.487,60.112 38.05,60.675 C20.2@38.05,61.19
NetC21_1: C21.1 U9.27 | length 1.9
  Top Layer w0.125: v1(35.925,60.525) U9.27@35.925,61.65
  Bottom Layer w0.125: C21.1@35.75,61.19 35.75,60.7 v1(35.925,60.525)
NetC22_1: C22.1 U8.2 | length 2.1
  Top Layer w0.125: U8.2@25.725,54.005 v1(25.725,55.13)
  Bottom Layer w0.125: C22.1@25.075,54.46 25.725,55.11 v1(25.725,55.13)
NetC22_2: C22.2 U8.1 | length 1.8
  Top Layer w0.125: v1(25.075,52.88) U8.1@25.075,54.005
  Bottom Layer w0.125: v1(25.075,52.88) C22.2@25.075,53.54
NetC23_1: C23.1 U9.2 | length 1.9
  Top Layer w0.125: U9.2@35.925,55.85 v1(35.925,56.975)
  Bottom Layer w0.125: C23.1@35.6,56.31 35.925,56.635 v1(35.925,56.975)
NetC23_2: C23.2 U9.1 | length 1.9
  Top Layer w0.125: v1(35.275,54.725) U9.1@35.275,55.85
  Bottom Layer w0.125: v1(35.275,54.725) 35.275,55.065 C23.2@35.6,55.39
NetC24_2: C24.2 U8.3 | length 1.8
  Top Layer w0.125: U8.3@26.375,54.005 v1(26.375,55.13)
  Bottom Layer w0.125: v1(26.375,55.13) 26.4,55.105 C24.2@26.4,54.46
NetC25_2: C25.2 U9.3 | length 1.9
  Top Layer w0.125: v1(36.575,54.725) U9.3@36.575,55.85
  Bottom Layer w0.125: v1(36.575,54.725) 36.575,55.115 C25.2@36.85,55.39
NetC28_2: C28.2 R39.2 U10.46 X1.1 | length 7
  Top Layer w0.125: C28.2@26.625,40.89 27.165,40.35 27.525,40.35 X1.1@28.1,39.775 28.32,39.555 R39.2@28.32,37.7 28.32,37.43 28.6,37.15 29.693,37.15 30.125,36.718 U10.46@30.125,36.2
NetC29_2: C29.2 J13.1 | length 3.4
  Top Layer w0.4: C29.2@7.65,16.865 8.907,16.865 8.972,16.8 10.91,16.8 J13.1@11,16.89
NetC30_2: C30.2 R39.1 U10.45 X1.3 | length 8.5
  Top Layer w0.125: C30.2@29.81,43.05 29.81,42.265 X1.3@30.4,41.675 29.25,40.525 29.25,39.683 28.938,39.371 28.938,38.042 R39.1@29.28,37.7 29.496,37.7 30.609,36.588 30.625,36.588 U10.45@30.625,36.2
NetC42_2: C42.2 C43.2 C44.2 C45.2 L2.2 U10.1 U10.12 U10.47 | length 10.3
  Top Layer w0.125: C45.2@25.835,35.5 C42.2@25.835,36.625 L2.2@25.835,37.855 ; C45.2@25.96,35.625 v1(26.625,35.625) 27,35.625 27.125,35.5 U10.1@28.425,35.5 ; C44.2@27.125,37.665 v1(27.125,37.002) 27.253,36.875 29.551,36.875 29.625,36.801 U10.47@29.625,36.2
  Top Layer w0.25: C43.2@27.04,29.625 v1(27.75,29.625) 28.125,30 U10.12@28.425,30
NetC46_2: C46.2 C47.2 C48.2 C49.2 L3.1 U10.16 U10.34 U10.40 | length 12.3
  Top Layer w0.125: C46.2@29.75,27.335 v1(29.75,28) 30.625,28.875 U10.16@30.625,29.3 ; U10.40@33.125,36.2 33.125,36.925 34.478,38.278 34.478,38.627 34.81,38.96 C47.2@34.9,38.96 ; L3.1@36.25,27.355 36.375,27.48 v1(36.375,28) ; C48.2@37.79,34.5 v1(37.125,34.5) ; v1(37.125,34.5) U10.34@35.325,34.5 v1(37.125,34.5)
  Top Layer w0.4: C47.2@34.9,38.96 C47.2@35,38.96 35.64,38.96 v1(35.65,38.95)
  Bottom Layer w0.125: C49.2@36.375,27.335 v1(36.375,28)
NetC50_2: C50.2 C51.2 C52.2 C53.2 C54.2 C55.2 C56.2 L4.1 U10.14 U10.18 U10.23 U10.26 U10.30 U10.39 | length 17.7
  Top Layer w0.125: C50.2@28.625,27.335 28.625,27.875 29.625,28.875 U10.14@29.625,29.3 ; C51.2@31.625,27.46 v1(31.625,28) U10.18@31.625,29.3 ; U10.39@33.625,36.2 33.625,36.75 v1(34.125,37.25) 34.25,37.375 36.29,37.375 ; U10.23@34.125,29.3 34.125,28.725 34.437,28.413 34.962,28.413 35.375,28 v1(35.375,27.375) 35.375,27.335 C52.2@34.625,27.335 ; U10.26@35.325,30.5 35.875,30.5 36.125,30.25 v1(36.5,30.25) C53.2@37.04,29.71 ; U10.30@35.325,32.5 35.875,32.5 36.375,32 v1(36.75,32) C54.2@37.165,32 ; C56.2@36.29,36.875 36.29,37.375 ; L4.1@36.29,39.25 36.29,37.375
  other v1: 28.625,28
NetC60_2: C60.2 C61.2 L5.2 U10.44 | length 7.6
  Top Layer w0.125: v1(29.35,39.2) 29.35,38.526 29.778,38.098 29.778,37.773 30.45,37.1 30.8,37.1 31.125,36.775 U10.44@31.125,36.2
  Bottom Layer w0.2: L5.2@27.2,41.02 27.2,41.014 27.85,40.364 27.85,40.21 C60.2@28.16,39.9
  Bottom Layer w0.3: C60.2@28.16,39.9 28.86,39.2 v1(29.35,39.2) 29.16,39.01 C61.2@29.16,38.6
NetC63_1: C63.1 R67.1 U13.32 X2.3 | length 7.6
  Bottom Layer w0.125: C63.1@29.535,41.05 X2.3@30.9,41.05 31.075,41.05 32,40.125 32,38.75 31.75,38.5 31.75,36.475 31.875,36.35 U13.32@31.875,35.55
NetC64_1: C64.1 R67.2 U13.33 X2.1 | length 5.7
  Bottom Layer w0.125: U13.33@32.375,35.55 32.375,36.75 32.73,37.105 32.73,39.08 X2.1@33.1,39.45 33.44,39.79 C64.1@34.5,39.79
NetC66_2: C66.2 C67.2 L9.2 R72.1 U12.8 U15.S | length 13.2
  Top Layer w0.125: L9.2@36.25,17.475 v1(36.25,18.5)
  Bottom Layer w0.125: v1(36.25,18.5) 36.4,18.35 U15.S@38.3,18.35 38.663,18.713 38.663,19.437 38.25,19.85 C67.2@38.25,23.29 39.125,23.29 C66.2@39.375,23.54 41.23,23.54 U12.8@41.345,23.425 41.345,21.885 R72.1@41.375,21.855
NetC68_2: C68.2 C71.2 L7.2 U14.8 | length 11.7
  Top Layer w0.125: v1(28.875,16.375) C71.2@28.875,17.165 L7.2@30.19,17.165
  Bottom Layer w0.125: U14.8@23.22,21.8 23.187,21.767 23.187,19.579 24.017,18.75 C68.2@24.665,18.75 24.665,18.125 24.955,17.835 27.415,17.835 v1(28.875,16.375)
NetC69_2: C69.2 C70.2 L6.2 U14.5 | length 9.1
  Top Layer w0.125: v1(27.125,19.5) 30.375,19.5 32.4,17.475 L6.2@32.5,17.475
  Bottom Layer w0.125: C70.2@27.03,20.26 U14.5@27.03,21.8 ; C69.2@27.125,18.79 v1(27.125,19.5) C70.2@27.125,20.165
NetC72_2: C72.2 C73.2 C74.2 C75.2 C76.2 C77.2 L17.1 U13.5 U13.10 U13.15 U13.23 U13.29 U13.36 | length 21.4
  Bottom Layer w0.125: C77.2@25.835,32.625 v1(26.625,32.625) 27.625,32.625 27.75,32.75 U13.23@29.075,32.75 ; v1(28.5,36.375) 30.25,36.375 30.375,36.25 U13.29@30.375,35.55 ; C73.2@30.75,27.335 v1(30.75,28) 30.75,28.5 31.375,29.125 U13.15@31.375,29.95 ; U13.10@33.875,29.95 33.875,28.75 v1(34.625,28) C74.2@34.625,27.335 ; U13.36@33.875,35.55 34.175,35.55 35.5,36.875 v1(35.625,36.875) C76.2@36.29,36.875 ; v1(36.375,32.75) 37.125,32.75 37.29,32.585 C75.2@37.29,32.5
  Bottom Layer w0.25: L17.1@25.5,38.15 25.985,37.665 C72.2@27.125,37.665 27.585,37.665 28.5,36.75 v1(28.5,36.375) ; U13.5@34.675,32.75 v1(36.375,32.75)
NetC78_2: C78.2 U13.14 | length 2.9
  Bottom Layer w0.125: C78.2@31.75,27.335 32.125,27.71 32.125,28.75 31.875,29 U13.14@31.875,29.95
NetC79_2: C79.2 U13.34 | length 2.8
  Bottom Layer w0.125: U13.34@32.875,35.55 32.875,36.25 33.665,37.04 C79.2@33.665,38
NetC84_2: C84.2 U16.37 | length 2.1
  Bottom Layer w0.138: U16.37@57.875,13.55 U16.37@57.875,13.65 57.875,15.275 57.94,15.34 C84.2@57.94,15.6
NetC86_2: C86.2 P1.18 R85.2 R87.2 U16.38 | length 17.5
  Top Layer w0.125: R85.2@47.895,12.25 47.895,12.77 48,12.875 48.75,12.875 50.112,14.237 55.851,14.237 56.101,13.987 58.071,13.987 58.25,13.809 58.25,13.27 R87.2@58.23,13.25 v1(58.875,13.25) ; R85.2@47.915,12.25 C86.2@47.915,11.125 47.915,10.585 48.375,10.125 P1.18@48.375,8.5
  Bottom Layer w0.125: U16.38@58.375,13.65 58.775,13.25 v1(58.875,13.25)
NetC87_1: C87.1 U17.11 | length 3.7
  Bottom Layer w0.125: U17.11@70.25,24.05 70.25,23.313 70.137,23.2 70.137,22.629 70.379,22.387 70.613,22.387 71.5,21.5 C87.1@71.5,21.085
NetC87_2: C87.2 L18.1 R92.2 | length 2.2
  Bottom Layer w0.125: C87.2@71.5,20.165 L18.1@71.5,19.105 R92.2@72.625,19.105
NetC88_1: C88.1 U17.12 | length 3.2
  Bottom Layer w0.125: U17.12@69.75,24.05 69.75,21.71 C88.1@70.375,21.085
NetC88_2: C88.2 L19.1 R91.2 | length 2.2
  Bottom Layer w0.125: L19.1@69.25,19.105 R91.2@70.375,19.105 C88.2@70.375,20.165
NetC89_2: C89.2 U17.18 | length 1.7
  Bottom Layer w0.125: C89.2@65.96,24.5 65.96,24.96 66.25,25.25 U17.18@67.05,25.25
NetC90_2: C90.2 U17.10 | length 3.7
  Bottom Layer w0.125: U17.10@70.75,24.05 70.75,23.5 72.625,21.625 C90.2@72.625,21.085
NetC91_1: C91.1 L20.2 | length 1.1
  Bottom Layer w0.125: L20.2@68.125,19.105 C91.1@68.125,20.165
NetC91_2: C91.2 U17.13 | length 3.4
  Bottom Layer w0.125: C91.2@68.125,21.085 68.125,22.25 69.25,23.375 U17.13@69.25,24.05
NetC92_1: C92.1 L21.2 | length 1.1
  Bottom Layer w0.125: L21.2@67,19.105 C92.1@67,20.165
NetC92_2: C92.2 U17.14 | length 3.7
  Bottom Layer w0.125: C92.2@67,21.085 67,21.625 68.75,23.375 U17.14@68.75,24.05
NetC93_1: C93.1 L22.2 | length 1.1
  Bottom Layer w0.125: L22.2@65.875,19.105 C93.1@65.875,20.165
NetC93_2: C93.2 U17.15 | length 3.9
  Bottom Layer w0.125: C93.2@65.875,21.085 68.25,23.46 U17.15@68.25,24.05
NetC94_2: C94.2 R94.2 U17.16 | length 4.6
  Bottom Layer w0.125: R94.2@64.75,21.105 64.94,21.105 C94.2@65.875,22.04 66.415,22.04 67.75,23.375 U17.16@67.75,24.05
NetC97_2: C97.2 C98.2 L26.2 U17.5 | length 5.5
  Bottom Layer w0.25: U17.5@71.95,26.25 73.25,26.25 C97.2@73.46,26.04 ; L26.2@77.15,26.4 76.79,26.04 C98.2@75.5,26.04 C97.2@73.5,26.04 ; C97.2@73.46,26.04 C97.2@73.5,26.04 ; C97.2@73.46,26.04 C97.2@73.5,26.04
NetC102_1: C102.1 D8.2 J22.2 | length 5.1
  Top Layer w0.25: D8.2@77.8,13.25 C102.1@78.8,13.25 78.8,9.7 J22.2@79.2,9.3
NetC102_2: C102.2 L24.2 | length 23.7
  Top Layer w0.125: v1(78.75,14.15) 80.15,14.15 80.4,13.9 C102.2@80.4,13.25
  Layer 3 w0.125: v1(73.5,29.75) 75.325,27.925 75.325,20.1 74.95,19.725 74.95,18.775 74.325,18.15 74.325,15.825 76.438,13.712 78.312,13.712 v1(78.75,14.15)
  Bottom Layer w0.125: L24.2@73.5,28.98 v1(73.5,29.75)
NetC103_1: C103.1 D7.2 J22.3 | length 5.3
  Top Layer w0.25: D7.2@67.075,13.25 v1(67.075,12.35) 67.075,11.525 67.7,10.9 J22.3@67.7,9
  Bottom Layer w0.25: C103.1@66.3,12.35 v1(67.075,12.35)
NetC103_2: C103.2 L25.2 | length 13.7
  Layer 5 w0.125: v1(67.45,13.95) 67.45,14.7 69.825,17.075 69.825,18.096 73.5,21.771 v1(73.5,23.35)
  Bottom Layer w0.125: C103.2@66.3,13.95 v1(67.45,13.95) ; v1(73.5,23.35) L25.2@73.5,24.02
NetC104_2: C104.2 R48.1 | length 23.4
  Top Layer w0.15: R48.1@37.28,41.15 38.73,42.6 40.7,42.6 41.2,42.1 42.4,42.1 45.25,39.25 45.25,28.1 v1(45.7,27.65)
  Bottom Layer w0.15: v1@45.701,27.65 46.75,26.601 C104.2@46.75,26.41
NetC107_1: C107.1 U23.10 | length 2.3
  Bottom Layer w0.2: U23.10@76.95,53.8 79.04,53.8 C107.1@79.2,53.96
NetC107_2: C107.2 R142.1 | length 1.5
  Bottom Layer w0.2: C107.2@79.2,53.04 79.54,52.7 R142.1@80.6,52.7
NetC108_1: C108.1 U23.8 | length 1.4
  Bottom Layer w0.15: U23.8@76.95,54.8 77.318,54.8 78.04,55.522 C108.1@78.04,55.55
NetC109_2: C109.2 U23.11 | length 1.2
  Bottom Layer w0.2: U23.11@76.95,53.3 77.33,52.92 C109.2@78,52.92
NetC110_2: C110.2 U23.6 | length 1.2
  Bottom Layer w0.15: C110.2@75.75,56.79 75.75,56.3 76.15,55.9 U23.6@76.15,55.75
NetC118_2: C118.2 R131.1 U17.30 | length 3.2
  Bottom Layer w0.125: R131.1@69.53,30.9 C118.2@70.59,30.9 70.59,30.348 70.263,30.021 70.263,28.962 U17.30@70.25,28.95
NetCAD1_5: CAD1.5 R149.2 R151.2 | length 7.1
  Bottom Layer w0.15: CAD1.5@11.535,35.16 12.41,35.16 13.8,36.55 15.07,36.55 R151.2@16.22,35.4 R149.2@16.22,34
NetCAD2_5: CAD2.5 R150.2 R152.2 | length 4.9
  Bottom Layer w0.2: CAD2.5@11.935,51.26 13.89,51.26 14.42,50.73 R152.2@15.2,50.73 R150.2@15.2,52.12
NetD1_A: D1.A R12.1 | length 2.6
  Top Layer w0.3: R12.1@89.98,13.5 91.75,13.5 D1.A@91.75,12.7
NetD2_K: D2.K R11.1 R13.1 | length 7.1
  Bottom Layer w0.5: R11.1@83.92,19.55 84.22,19.55 85.07,20.4 85.07,22.2 ; R13.1@84.07,22.23 85.04,22.23 85.07,22.2 ; D2.K@84.07,24.25 84.67,24.25 85.07,23.85 85.07,22.2
NetD3_K: D3.K R86.1 | length 2.2
  Top Layer w0.125: R86.1@51.855,11.125 D3.K@54.1,11.125
NetD4_A: D4.A R119.1 | length 3.4
  Top Layer w0.2: D4.A@14.1,60.2 14.1,58.05 v1(14.25,57.9)
  Bottom Layer w0.2: v1(14.25,57.9) 14.7,58.35 R119.1@14.7,58.77
NetD5_A: D5.A R120.1 | length 4.2
  Top Layer w0.2: v1(10.7,61.35) 10.7,61 D5.A@11.5,60.2
  Bottom Layer w0.2: v1(10.7,61.35) 11.298,60.752 12.372,60.752 R120.1@12.97,61.35
NetD6_A: D6.A R121.1 | length 4.7
  Top Layer w0.2: v1(7.45,60.25) 8.85,60.25 D6.A@8.9,60.2
  Bottom Layer w0.2: v1(7.45,60.25) 8.1,60.9 9.55,60.9 9.83,61.18 R121.1@9.83,61.6
NetD10_2: D10.2 J16.1 L9.1 | length 12.1
  Top Layer w0.125: v1(35.625,5.25) 36.125,5.75 36.125,14.625 36.25,14.75 L9.1@36.25,15.775
  Bottom Layer w0.125: J16.1@35.6,4.5 35.6,5.225 v1(35.625,5.25) D10.2@35.625,5.825
NetD11_A: D11.A R133.2 | length 2.1
  Bottom Layer w0.2: R133.2@29.8,50.42 31.88,50.42 D11.A@31.9,50.4
NetD11_K: D11.K Q5.D | length 3.5
  Bottom Layer w0.2: D11.K@31.9,53 31.9,53.475 34.665,53.475 Q5.D@34.85,53.29
NetFIL1_1: FIL1.1 J1.1
NetJ2_1: J2.1 R8.1 | length 2
  Bottom Layer w0.5: R8.1@96.05,8.57 97.97,8.57 J2.1@98,8.6
NetJ3_2: J3.2 R77.1 R123.1 SW2.3 SW2.4 | length 57.2
  Top Layer w0.125: v1(17.4,20.65) 17.4,20.95 SW2.3@17.4,21.525 ; v1(21.45,21.3) 21.675,21.525 SW2.4@23.2,21.525
  Layer 8 w0.125: J3.2@6,60.55 6.35,60.55 7.1,59.8 7.1,53.2 6.887,52.987 6.887,46.987 5.613,45.713 5.613,31.737 7.3,30.05 14.25,30.05 v1(17,27.3)
  Bottom Layer w0.125: J3.2@6,60.55 J3.2@6.032,60.55 ; v1(17,27.3) 17,23.55 17.262,23.288 17.262,22.708 R123.1@17.42,22.55 R77.1@17.42,21.5 17.4,21.48 v1@17.4,20.7 ; v1(17.4,20.65) v1@17.4,20.7 ; v1(21.45,21.3) 20.55,21.3 19.95,20.7 v1@17.4,20.7
NetJ7_5: J7.5 R35.2 | length 49.9
  Layer 3 w0.103: v1(76.875,6.625) 76.875,6.25 76.925,6.2 77.25,6.2 77.3,6.25 77.3,6.75 81.125,10.575 81.125,13.875 89.225,21.975 89.225,31.75 88.598,32.377 88.598,46.723 v1(89.5,47.625)
  Bottom Layer w0.2: J7.5@76.875,5.275 v1(76.875,6.625) ; R35.2@88.73,47.65 89.475,47.65 v1(89.5,47.625)
NetJ13_D1: J13.D1 R45.1 | length 8.7
  Bottom Layer w0.125: J13.D1@10.086,3.936 14.625,8.475 14.625,8.875 15.52,9.77 R45.1@16.125,9.77
NetJ13_D3: J13.D3 R38.1 | length 7.5
  Bottom Layer w0.125: R38.1@17.375,9.77 17.855,9.77 19.625,8 19.625,5.115 J13.D3@20.804,3.936
NetJ15_A1: J15.A1 L7.1 | length 2.8
  Top Layer w0.125: J15.A1@30.5,13 L7.1@30.5,15.775
NetJ15_A4: J15.A4 L13.2 | length 3.1
  Top Layer w0.125: J15.A4@37.5,13 37.5,14.25 38.25,15 L13.2@38.25,15.775
NetJ15_B1: J15.B1 L6.1 | length 6.2
  Top Layer w0.125: J15.B1@30.5,10.38 31.75,11.63 31.75,13.5 32.5,14.25 L6.1@32.5,15.775
NetJ15_B4: J15.B4 L12.2 | length 10.1
  Top Layer w0.125: J15.B4@37.5,10.38 36.5,11.38 36.5,14.125 37.25,14.875 37.25,16.5 37.375,16.625 39.85,16.625 L12.2@40.25,17.025
NetJ16_5: J16.5 L15.2 | length 18.6
  Top Layer w0.125: v1@25.75,16.775 L15.2@27.225,16.775
  Bottom Layer w0.125: v1@25.75,16.775 27.75,16.775 28.625,15.9 29.75,15.9 31.5,14.15 31.5,8.65 33,7.15 33,4.55 J16.5@33,4.525
  other v1: 25.75,16.75
NetJ19_2: J19.2 L30.2 | length 1.8
  Top Layer w0.104: L30.2@32.025,63.625 L30.2@32.025,63.65 31.875,63.8 31.875,64.125 32.375,64.625 J19.2@32.375,65.2
NetJ19_3: J19.3 L30.3 | length 1.8
  Top Layer w0.104: J19.3@31.125,65.2 31.125,64.675 31.6,64.2 31.6,63.75 L30.3@31.475,63.625
NetJ19_5: J19.5 L31.2 | length 1.9
  Top Layer w0.104: L31.2@28.225,63.625 L31.2@28.275,63.625 ; L31.2@28.275,63.65 28.138,63.788 28.138,64.138 28.625,64.625 J19.5@28.625,65.2
NetJ19_6: J19.6 L31.3 | length 1.8
  Top Layer w0.104: J19.6@27.375,65.2 27.375,64.675 27.85,64.2 27.85,63.75 L31.3@27.725,63.625
NetJ19_8: J19.8 L32.2 | length 1.9
  Top Layer w0.104: L32.2@24.475,63.625 L32.2@24.525,63.625 ; L32.2@24.525,63.65 24.388,63.788 24.388,64.138 24.875,64.625 J19.8@24.875,65.2
NetJ19_9: J19.9 L32.3 | length 1.8
  Top Layer w0.104: J19.9@23.625,65.2 23.625,64.675 24.1,64.2 24.1,63.75 L32.3@23.975,63.625
NetJ19_11: J19.11 L33.2 | length 1.9
  Top Layer w0.104: L33.2@20.425,63.625 20.425,64.025 21.125,64.725 J19.11@21.125,65.2
NetJ19_12: J19.12 L33.3 | length 1.7
  Top Layer w0.104: L33.3@19.875,63.65 19.875,63.936 20.1,64.161 20.1,64.975 J19.12@19.875,65.2
NetJ19_14: J19.14 L34.2 | length 1.9
  Top Layer w0.104: L34.2@16.975,63.625 L34.2@17.025,63.625 ; L34.2@17.025,63.65 16.862,63.813 16.862,64.113 17.375,64.625 J19.14@17.375,65.2
NetJ19_15: J19.15 L34.3 | length 1.8
  Top Layer w0.104: J19.15@16.125,65.2 16.125,64.675 16.6,64.2 16.6,63.75 L34.3@16.475,63.625
NetJ19_20: J19.20 L35.2 | length 2.9
  Top Layer w0.5: L35.2@7.25,64.6 7.85,65.2 J19.20@9.875,65.2
NetJ23_4: J23.4 R84.2 | length 2.2
  Top Layer w0.4: J23.4@20.825,47 v1(22.55,47)
  Bottom Layer w0.4: v1(22.55,47) R84.2@23.07,47
NetJ23_6: J23.6 R101.2 | length 2.6
  Top Layer w0.254: J23.6@20.825,43 20.825,43.375 v1(21.15,43.7)
  Bottom Layer w0.254: v1(21.15,43.7) 21.25,43.6 R101.2@22.87,43.6
NetJ24_7: J24.7 R135.1 | length 3.2
  Top Layer w0.25: v1(39.75,41.65) 39.975,41.425 J24.7@39.975,41
  Bottom Layer w0.25: R135.1@37.45,41.38 37.72,41.65 v1(39.75,41.65)
NetJ24_10: J24.10 R130.1 | length 1.6
  Top Layer w0.4: J24.10@42.825,35 43.45,34.375 R130.1@43.45,33.63
NetJ30_1: J30.1 R204.2 R257.2 | length 13.1
  Top Layer w0.125: J30.1@2.1,7.4 3.15,7.4 4.15,8.4 4.15,11.78 R257.2@4.62,12.25
  Bottom Layer w0.15: J30.1@2.1,7.4 3.25,7.4 3.95,8.1 3.95,11.58 R204.2@4.62,12.25
NetJ30_2: J30.2 R205.2 R258.2 | length 12.9
  Top Layer w0.125: J30.2@2.1,8.65 3.2,8.65 3.85,9.3 3.85,12.65 4.6,13.4 R258.2@4.62,13.4
  Bottom Layer w0.15: J30.2@2.1,8.65 3.2,8.65 3.6,9.05 3.6,12.45 4.55,13.4 R205.2@4.62,13.4
NetJ30_3: J30.3 R206.2 R259.2 | length 12.9
  Top Layer w0.125: J30.3@2.1,9.9 3.15,9.9 3.6,10.35 3.6,13.75 4.45,14.6 R259.2@4.62,14.6
  Bottom Layer w0.15: J30.3@2.1,9.9 2.962,9.9 3.263,10.2 3.263,13.613 4.25,14.6 R206.2@4.62,14.6
NetJ31_2: J31.2 L36.2 | length 1.8
  Bottom Layer w0.104: J31.2@11.125,65.2 11.125,64.575 11.5,64.2 11.5,63.7 L36.2@11.425,63.625
NetJ31_3: J31.3 L36.3 | length 1.8
  Bottom Layer w0.104: L36.3@11.975,63.625 11.9,63.7 11.9,64.15 12.375,64.625 J31.3@12.375,65.2
NetJ31_5: J31.5 L38.2 | length 1.8
  Bottom Layer w0.104: J31.5@14.875,65.2 14.875,64.625 15.3,64.2 15.3,63.7 L38.2@15.225,63.625
NetJ31_6: J31.6 L38.3 | length 1.8
  Bottom Layer w0.104: L38.3@15.775,63.65 15.625,63.8 15.625,64.225 16.125,64.725 J31.6@16.125,65.2
NetJ31_8: J31.8 L40.2 | length 1.7
  Bottom Layer w0.104: L40.2@18.625,63.625 L40.2@18.625,63.65 18.625,63.925 18.75,64.05 18.75,65.075 J31.8@18.625,65.2
NetJ31_9: J31.9 L40.3 | length 1.9
  Bottom Layer w0.104: L40.3@19.175,63.625 L40.3@19.175,63.65 19.175,63.975 19.875,64.675 J31.9@19.875,65.2
NetJ31_11: J31.11 L42.2 | length 1.8
  Bottom Layer w0.104: J31.11@22.375,65.2 22.375,64.575 22.75,64.2 22.75,63.75 L42.2@22.625,63.625
NetJ31_12: J31.12 L42.3 | length 1.8
  Bottom Layer w0.104: L42.3@23.175,63.625 23.1,63.7 23.1,64.15 23.625,64.675 J31.12@23.625,65.2
NetJ31_14: J31.14 L44.2 | length 1.8
  Bottom Layer w0.104: J31.14@26.125,65.2 26.125,64.575 26.5,64.2 26.5,63.75 L44.2@26.375,63.625
NetJ31_15: J31.15 L44.3 | length 1.9
  Bottom Layer w0.104: L44.3@26.925,63.65 26.761,63.814 26.761,64.211 27.375,64.825 J31.15@27.375,65.2
NetJ31_20: J31.20 L45.2 | length 2.6
  Bottom Layer w0.5: J31.20@33.625,65.2 34.55,65.2 L45.2@35.7,64.05
NetL1_1: L1.1 R142.2 U23.2 U23.13 | length 4.3
  Bottom Layer w0.2: R142.2@80.6,54.3 v1(80.6,55)
  Bottom Layer w0.3: v1@74.65,53.8 v1(74.6,53.75) ; v1@74.75,53.8 U23.2@75.35,53.8 U23.13@76.15,53.8 ; v1(74.6,53.75) v1(74.15,53.75) v1(74.15,53.15) v1(74.6,53.15) v1(74.6,53.75)
  other v1: 72.5,56.65 72.5,57.15 72.5,57.65 72.5,58.15
NetL8_1: L8.1 U13.1 | length 2.2
  Bottom Layer w0.125: U13.1@34.675,34.75 35,34.75 35.5,35.25 35.5,35.5 35.9,35.9 L8.1@36.275,35.9
NetL8_4: L8.4 U13.2 | length 2
  Bottom Layer w0.125: U13.2@34.675,34.25 35.125,34.25 35.975,35.1 L8.4@36.275,35.1
NetL11_1: L11.1 U13.3 | length 1.8
  Bottom Layer w0.125: U13.3@34.675,33.75 35.5,33.75 36.025,34.275 L11.1@36.275,34.275
NetL11_4: L11.4 U13.4 | length 1.7
  Bottom Layer w0.125: U13.4@34.675,33.25 35.75,33.25 36,33.5 L11.4@36.275,33.5
NetL14_1: L14.1 U13.6 | length 3.3
  Bottom Layer w0.125: U13.6@34.675,32.25 35.5,32.25 36.375,31.375 37.375,31.375 L14.1@37.525,31.525
NetL14_4: L14.4 U13.7 | length 3.1
  Bottom Layer w0.125: U13.7@34.675,31.75 35.5,31.75 36.525,30.725 L14.4@37.4,30.725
